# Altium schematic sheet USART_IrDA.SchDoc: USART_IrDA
size A3; DocumentNumber: MB1144; Revision: C-02; SheetNumber: 9; SheetTotal: 25; Project: STM32L476G-EVAL
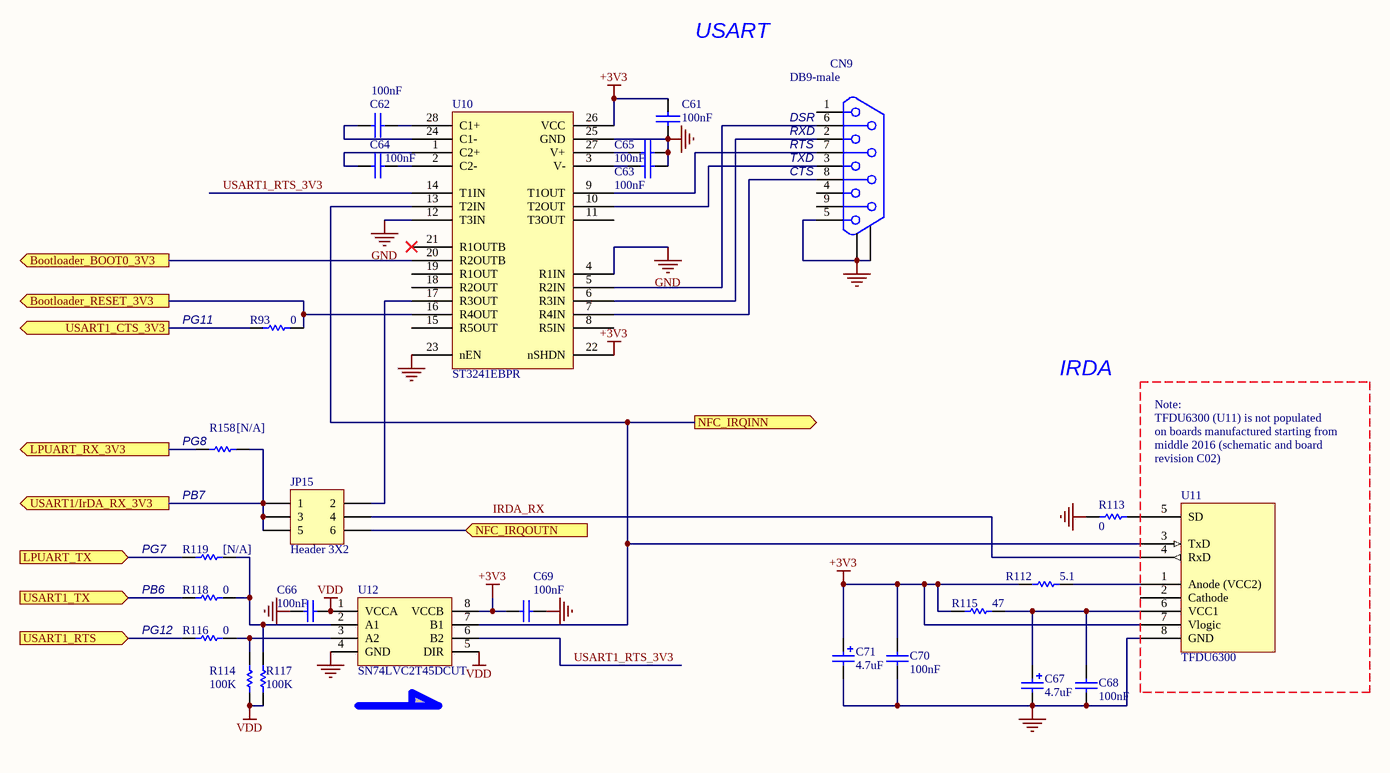
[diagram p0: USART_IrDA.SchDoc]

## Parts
C61  100nF  [0402C]
C62  100nF  [0402C]
C63  100nF  [0402C]
C64  100nF  [0402C]
C65  100nF  [0402C]
C66  100nF  [0402C]
C67  4.7uF  [TAN-A]
C68  100nF  [0402C]
C69  100nF  [0402C]
C70  100nF  [0402C]
C71  4.7uF  [TAN-A]
CN9  DB9-male  [DB9/M]
JP15  Header 3X2  [HDR_2X3_2R54]
R93  0  [0603R]
R112  5.1  [0402R]
R113  0  [0603R]
R114  100K  [0402R]
R115  47  [0402R]
R116  0  [0603R]
R117  100K  [0402R]
R118  0  [0603R]
R119  [N/A]  [0603R]
R158  [N/A]  [0603R]
U10  ST3241EBPR  [SSOP28_0R65_10R2X7R8]
U11  TFDU6300  [IR_VISHAY3]
U12  SN74LVC2T45DCUT  [USOP8_0R5_2X3R1]

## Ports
Bootloader_BOOT0_3V3 (out), Bootloader_RESET_3V3 (out), LPUART_RX_3V3 (out), LPUART_TX (in), NFC_IRQINN (out), NFC_IRQOUTN (in), USART1/IrDA_RX_3V3 (out), USART1_CTS_3V3 (out), USART1_RTS (in), USART1_TX (in)

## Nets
+3V3: C61.2 C69.2 C70.2 C71.1 R112.1 R115.1 U10.22(nSHDN) U10.26(VCC) U11.7(Vlogic) U12.8(VCCB)
GND: C61.1 C63.2 C65.2 C66.1 C67.2 C68.1 C69.1 C70.1 C71.2 CN9.5 CN9.10 CN9.11 R113.2 U10.4(R1IN) U10.12(T3IN) U10.23(nEN) U10.25(GND) U11.8(GND) U12.4(GND)
VDD: C66.2 R114.2 R117.2 U12.1(VCCA) U12.5(DIR)
Bootloader_BOOT0_3V3: U10.20(R2OUTB) ; port Bootloader_BOOT0_3V3
Bootloader_RESET_3V3: R93.1 U10.16(R4OUT) ; port Bootloader_RESET_3V3
IRDA_RX: JP15.4 U11.4(RxD)
LPUART_RX_3V3: R158.2 ; port LPUART_RX_3V3
LPUART_TX: R119.2 ; port LPUART_TX
NFC_IRQINN: U10.13(T2IN) U11.3(TxD) U12.7(B1) ; port NFC_IRQINN
NFC_IRQOUTN: JP15.6 ; port NFC_IRQOUTN
USART1/IrDA_RX_3V3: JP15.1 JP15.3 JP15.5 R158.1 ; port USART1/IrDA_RX_3V3
USART1_CTS_3V3: R93.2 ; port USART1_CTS_3V3
USART1_RTS: R116.2 ; port USART1_RTS
USART1_RTS_3V3: U10.14(T1IN) U12.6(B2)
USART1_TX: R118.2 ; port USART1_TX
NetC62_1: C62.1 U10.24(C1-)
NetC62_2: C62.2 U10.28(C1+)
NetC63_1: C63.1 U10.3(V-)
NetC64_1: C64.1 U10.1(C2+)
NetC64_2: C64.2 U10.2(C2-)
NetC65_1: C65.1 U10.27(V+)
NetC67_1: C67.1 C68.2 R115.2 U11.6(VCC1)
NetCN9_2: CN9.2 U10.6(R3IN)
NetCN9_3: CN9.3 U10.10(T2OUT)
NetCN9_6: CN9.6 U10.5(R2IN)
NetCN9_7: CN9.7 U10.9(T1OUT)
NetCN9_8: CN9.8 U10.7(R4IN)
NetJP15_2: JP15.2 U10.17(R3OUT)
NetR112_2: R112.2 U11.1(Anode_(VCC2))
NetR113_1: R113.1 U11.5(SD)
NetR114_1: R114.1 R116.1 U12.3(A2)
NetR117_1: R117.1 R118.1 R119.1 U12.2(A1)

Not connected (* = marked no-connect by the designer): CN9 1 4 9; U10 8(R5IN) 11(T3OUT) 15(R5OUT) 18(R2OUT) 19(R1OUT) 21(R1OUTB)*; U11 2(Cathode)

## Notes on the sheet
- USART
- (near CN9) RXD
- (near CN9) RTS
- (near CN9) TXD
- (near CN9) DSR
- (near CN9) CTS
- PG11
- IRDA
- PB7
- (near R158) PG8
- Note:
  TFDU6300 (U11) is not populated
  on boards manufactured starting from
  middle 2016 (schematic and board revision C02)
- PG7
- PG12
- PB6

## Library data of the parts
C61-C65 = CAP: Capacitor; Ordered by: Subcon; ECCN_US/EU: NA
C66 C68-C70 = CAP: Capacitor; Value: 100pF; Ordered by: Subcon; ECCN_US/EU: NA
C67 C71 = Cap Pol1: Polarized Capacitor (Radial); Value: 100pF; Ordered by: Subcon; ECCN_US/EU: NA
CN9 = DB9: Ordered by: Subcon; Comments: DB9 USART; ECCN_US/EU: NA
JP15 = Header 3X2: Header, 3-Pin, Dual row; ECCN_US/EU: NA; Ordered by: Subcon
R93 R112-R118 = Res1: Resistor; Value: 1K; Ordered by: Subcon; ECCN_US/EU: NA
R119 R158 = Res1: Resistor; Value: 1K; Ordered by: Subcon; ECCN_US/EU: NA; Fitted: NO
U10 = ST3241: Ordered by: ST; ECCN_US/EU: EAR99/NEC; Ref St: 9176312
U11 = TFDU4300: Manuf_1: Vishay; Ordered by: Subcon; ECCN_US/EU: EAR99/NEC; Fitted or not fitted: NO
U12 = SN74LVC2T45DCUT: Manuf_1: TI; Ordered by: Subcon; ECCN_US/EU: EAR99/NEC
